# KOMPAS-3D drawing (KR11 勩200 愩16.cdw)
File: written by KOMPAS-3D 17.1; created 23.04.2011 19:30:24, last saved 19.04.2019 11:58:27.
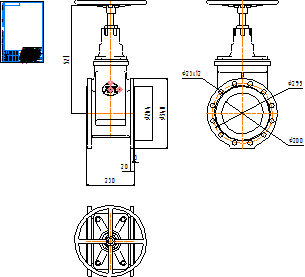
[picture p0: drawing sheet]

Sheet 1: A4, portrait

Title block, sheet 1: name: KR11 Ду200 Ру16; material: Внимание! Данный продукт является объектом авторского права ООО «Торговый Дом АДЛ». / Запрещается изменение, копирование, распространение / (в том числе путем копирования на другие сайты и ресурсы в Интернете) / или любое иное использование информации и объектов без предварительного / согласия правообладателя (ООО «Торговый Дом АДЛ»).; scale: 1:1; sheets: 1; organisation: ООО "Торговый дом АДЛ"; sheet format: A4; stored path: \\adlc.lan\data\АДЛ_ПКД\3D-модели\ADL production\Клиновые задвижки серии KR ГРАНАР\Клиновые задвижки KR11\KOMPAS 2D\KR11 Ду200 Ру16.cdw

Views: Спереди 4, Проекционный вид 5
Dimensions and other numbers on the sheet: 230; 20; 3; 521; 340; 264; 1:1; 1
